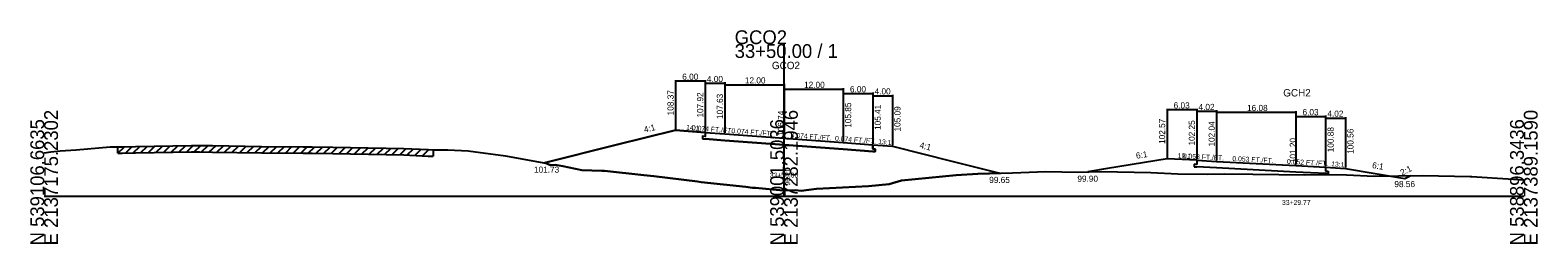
# Model space of a CAD drawing. Extents: x -14327 to 8886, y -10 to 39048.
# Drawn here: x 997.2 to 1302.8, y 6990.3 to 7033.7 of the extents above; entities that cross this region are included whole.
import ezdxf

# ---------------------------------------------------------------- set-up
doc = ezdxf.new("R2010")
doc.units = 0
for name, color, linetype in [('Level 20', 7, 'Continuous'), ('Level 5', 7, 'Continuous'), ('Level 53', 7, 'Continuous'), ('Level 54', 7, 'Continuous'), ('Level 55', 7, 'Continuous'), ('Level 7', 7, 'Continuous'), ('RD_GPK_XS_Cell', 7, 'Continuous'), ('RD_XS_EwShp', 7, 'Continuous'), ('RD_XS_ExGround', 7, 'Continuous'), ('RD_XS_ExPaveRet', 7, 'Continuous'), ('RD_XS_Pave', 7, 'Continuous'), ('RD_XS_TX_Baseline', 7, 'Continuous'), ('RD_XS_TX_Elev_EX', 7, 'Continuous'), ('RD_XS_TX_Elev_PR', 7, 'Continuous'), ('RD_XS_TX_Station', 7, 'Continuous')]:
    doc.layers.add(name, color=color, linetype=linetype)

msp = doc.modelspace()

# ---------------------------------------------------------------- linework, layer by layer
at = {"layer": 'Level 20'}
for p, q in [((1227.66, 7017.72), (1227.66, 7007.77)), ((1233.69, 7017.52), (1227.66, 7017.52)), ((1233.69, 7017.72), (1233.69, 7007.45)), ((1233.69, 7017.4), (1233.69, 7007.45)), ((1233.69, 7017.2), (1237.71, 7017.2)), ((1237.71, 7017.4), (1237.71, 7007.24)), ((1237.71, 7017.19), (1237.71, 7007.24)), ((1237.71, 7016.99), (1253.79, 7016.99)), ((1253.79, 7017.19), (1253.79, 7006.4)), ((1253.79, 7016.35), (1253.79, 7006.4)), ((1253.79, 7016.15), (1259.82, 7016.15)), ((1259.82, 7016.35), (1259.82, 7006.08)), ((1259.82, 7016.03), (1259.82, 7006.08)), ((1259.82, 7015.83), (1263.84, 7015.83)), ((1263.84, 7016.03), (1263.84, 7005.76)), ((1227.66, 7007.57), (1215.61, 7005.57)), ((1233.69, 7007.25), (1227.66, 7007.57)), ((1233.19, 7006.45), (1233.19, 7005.95)), ((1233.69, 7006.42), (1233.19, 7006.45)), ((1233.69, 7007.25), (1233.69, 7006.42)), ((1233.69, 7007.25), (1237.71, 7007.04)), ((1237.71, 7007.04), (1253.79, 7006.2)), ((1215.61, 7005.57), (1211.59, 7004.9)), ((1233.19, 7005.95), (1233.69, 7005.92)), ((1237.71, 7005.71), (1233.69, 7005.92)), ((1253.79, 7004.86), (1237.71, 7005.71)), ((1253.79, 7006.2), (1259.82, 7005.88)), ((1259.82, 7004.55), (1253.79, 7004.86)), ((1259.82, 7005.88), (1259.82, 7005.05)), ((1259.82, 7005.88), (1263.84, 7005.56)), ((1259.82, 7005.05), (1260.33, 7005.02)), ((1260.33, 7004.52), (1259.82, 7004.55)), ((1260.33, 7005.02), (1260.33, 7004.52)), ((1263.84, 7005.56), (1275.9, 7003.56)), ((1275.9, 7003.56), (1277.1, 7004.16))]:
    msp.add_line(p, q, dxfattribs=at)
at = {"layer": 'Level 5'}
for p, q in [((1134, 7012.92), (1134, 7012.09)), ((1133.5, 7012.13), (1133.5, 7011.63)), ((1134, 7012.09), (1133.5, 7012.13)), ((1133.5, 7011.63), (1134, 7011.59)), ((1138, 7011.29), (1134, 7011.59)), ((1150, 7010.4), (1138, 7011.29)), ((1162, 7009.52), (1150, 7010.4)), ((1168, 7009.07), (1162, 7009.52)), ((1168, 7010.41), (1168, 7009.57)), ((1168, 7009.57), (1168.5, 7009.54)), ((1168.5, 7009.54), (1168.5, 7009.04)), ((1168.5, 7009.04), (1168, 7009.07))]:
    msp.add_line(p, q, dxfattribs=at)
at = {"layer": 'Level 54'}
for p, q in [((1128, 7023.52), (1128, 7013.57)), ((1134, 7023.32), (1128, 7023.32)), ((1134, 7023.52), (1134, 7013.12)), ((1134, 7023.07), (1134, 7013.12)), ((1134, 7022.87), (1138, 7022.87)), ((1138, 7023.07), (1138, 7012.83)), ((1138, 7022.78), (1138, 7012.83)), ((1138, 7022.58), (1150, 7022.58)), ((1150, 7022.78), (1150, 7011.94)), ((1150, 7021.89), (1150, 7011.94)), ((1150, 7021.69), (1162, 7021.69)), ((1162, 7021.89), (1162, 7011.05)), ((1162, 7021), (1162, 7011.05)), ((1162, 7020.8), (1168, 7020.8)), ((1168, 7021), (1168, 7010.61)), ((1168, 7020.56), (1168, 7010.61)), ((1168, 7020.36), (1172, 7020.36)), ((1172, 7020.56), (1172, 7010.29))]:
    msp.add_line(p, q, dxfattribs=at)
at = {"layer": 'Level 7'}
for p, q in [((1128, 7013.37), (1116, 7010.37)), ((1134, 7012.92), (1128, 7013.37)), ((1116, 7010.37), (1101.45, 7006.73)), ((1168, 7010.41), (1172, 7010.09)), ((1172, 7010.09), (1184, 7007.09)), ((1184, 7007.09), (1193.74, 7004.65))]:
    msp.add_line(p, q, dxfattribs=at)
at = {"layer": 'RD_GPK_XS_Cell'}
for p, q in [((1150, 7000), (1150, 7030.81)), ((1000, 7000), (1150, 7000)), ((1150, 7000), (1300, 7000))]:
    msp.add_line(p, q, dxfattribs=at)
at = {"layer": 'RD_XS_EwShp'}
msp.add_lwpolyline([(1133.5, 7011.63), (1134, 7011.59), (1138, 7011.29), (1150, 7010.4), (1162, 7009.52), (1168, 7009.07), (1168.5, 7009.04), (1168.5, 7009.54), (1168, 7009.57), (1168, 7010.41), (1172, 7010.09), (1184, 7007.09), (1193.74, 7004.65), (1189.32, 7004.52), (1184.93, 7004.24), (1173.79, 7003.13), (1171.3, 7002.44), (1167.12, 7002.04), (1156.56, 7001.5), (1153.49, 7001.09), (1152.34, 7001.17), (1149.83, 7001.1), (1144.23, 7001.67), (1143.64, 7001.7), (1142.28, 7001.86), (1133.22, 7002.81), (1132.47, 7002.92), (1123.6, 7004.05), (1121.61, 7004.25), (1113.6, 7005.09), (1113.04, 7005.09), (1109.04, 7005.22), (1105.15, 7006.05), (1103.67, 7006.35), (1102.69, 7006.29), (1101.68, 7006.69), (1101.45, 7006.73), (1116, 7010.37), (1128, 7013.37), (1134, 7012.92), (1134, 7012.09), (1133.5, 7012.13)], close=True, dxfattribs=at)
at = {"layer": 'RD_XS_ExGround'}
for p, q in [((1003.23, 7009.16), (1006.47, 7009.37)), ((1006.47, 7009.37), (1013.36, 7010)), ((1013.36, 7010), (1014.93, 7009.97)), ((1014.93, 7009.97), (1015.82, 7009.99)), ((1015.82, 7009.99), (1018.52, 7010.06)), ((1018.52, 7010.06), (1029.84, 7010.24)), ((1029.84, 7010.24), (1031.46, 7010.27)), ((1031.46, 7010.27), (1034.1, 7010.23)), ((1034.1, 7010.23), (1044.07, 7010.08)), ((1044.07, 7010.08), (1052.51, 7010)), ((1052.51, 7010), (1054.35, 7009.97)), ((1054.35, 7009.97), (1058.55, 7009.9)), ((1058.55, 7009.9), (1072.92, 7009.67)), ((1072.92, 7009.67), (1077.83, 7009.42)), ((1077.83, 7009.42), (1078.88, 7009.37)), ((1078.88, 7009.37), (1081.85, 7009.35)), ((1081.85, 7009.35), (1085.98, 7009.15)), ((1000, 7008.78), (1001.38, 7008.95)), ((1001.38, 7008.95), (1003.23, 7009.16)), ((1085.98, 7009.15), (1093.5, 7008.17)), ((1093.5, 7008.17), (1093.84, 7008.11)), ((1093.84, 7008.11), (1101.68, 7006.69)), ((1101.68, 7006.69), (1102.69, 7006.29)), ((1102.69, 7006.29), (1103.67, 7006.35)), ((1103.67, 7006.35), (1105.15, 7006.05)), ((1105.15, 7006.05), (1109.04, 7005.22)), ((1109.04, 7005.22), (1113.04, 7005.09)), ((1113.04, 7005.09), (1113.6, 7005.09)), ((1113.6, 7005.09), (1121.61, 7004.25)), ((1121.61, 7004.25), (1123.6, 7004.05)), ((1123.6, 7004.05), (1132.47, 7002.92)), ((1173.79, 7003.13), (1184.93, 7004.24)), ((1184.93, 7004.24), (1189.32, 7004.52)), ((1189.32, 7004.52), (1196.33, 7004.73)), ((1196.33, 7004.73), (1203.07, 7004.95)), ((1203.07, 7004.95), (1209.6, 7004.86)), ((1209.6, 7004.86), (1214.22, 7004.96)), ((1214.22, 7004.96), (1224.39, 7004.75)), ((1224.39, 7004.75), (1229.82, 7004.49)), ((1229.82, 7004.49), (1235.87, 7004.46)), ((1235.87, 7004.46), (1239.24, 7004.48)), ((1239.24, 7004.48), (1245.06, 7004.47)), ((1245.06, 7004.47), (1255.59, 7004.31)), ((1255.59, 7004.31), (1259.61, 7004.4)), ((1259.61, 7004.4), (1264.04, 7004.31)), ((1264.04, 7004.31), (1269.64, 7004.03)), ((1269.64, 7004.03), (1279.54, 7004.2)), ((1279.54, 7004.2), (1289.09, 7003.97)), ((1289.09, 7003.97), (1289.47, 7003.97)), ((1289.47, 7003.97), (1291.46, 7003.83)), ((1291.46, 7003.83), (1300, 7003.29)), ((1132.47, 7002.92), (1133.22, 7002.81)), ((1133.22, 7002.81), (1142.28, 7001.86)), ((1142.28, 7001.86), (1143.64, 7001.7)), ((1143.64, 7001.7), (1144.23, 7001.67)), ((1144.23, 7001.67), (1149.83, 7001.1)), ((1149.83, 7001.1), (1152.34, 7001.17)), ((1152.34, 7001.17), (1153.49, 7001.09)), ((1153.49, 7001.09), (1156.56, 7001.5)), ((1156.56, 7001.5), (1167.12, 7002.04)), ((1167.12, 7002.04), (1171.3, 7002.44)), ((1171.3, 7002.44), (1173.79, 7003.13))]:
    msp.add_line(p, q, dxfattribs=at)
at = {"layer": 'RD_XS_ExPaveRet'}
for p, q in [((1014.93, 7008.67), (1016.3, 7010)), ((1014.93, 7008.67), (1014.93, 7009.97)), ((1016.47, 7008.71), (1017.85, 7010.04)), ((1018.02, 7008.75), (1019.39, 7010.08)), ((1019.56, 7008.78), (1020.92, 7010.1)), ((1021.11, 7008.8), (1022.47, 7010.12)), ((1022.65, 7008.83), (1024.01, 7010.15)), ((1024.2, 7008.85), (1025.56, 7010.17)), ((1025.74, 7008.88), (1027.1, 7010.2)), ((1027.29, 7008.9), (1028.65, 7010.22)), ((1028.83, 7008.92), (1030.19, 7010.25)), ((1030.38, 7008.95), (1031.73, 7010.27)), ((1031.92, 7008.96), (1033.24, 7010.24)), ((1033.47, 7008.94), (1034.79, 7010.22)), ((1035.01, 7008.91), (1036.33, 7010.2)), ((1036.56, 7008.89), (1037.88, 7010.17)), ((1038.1, 7008.87), (1039.42, 7010.15)), ((1039.65, 7008.85), (1040.97, 7010.13)), ((1041.19, 7008.83), (1042.51, 7010.11)), ((1042.74, 7008.8), (1044.06, 7010.08)), ((1044.28, 7008.78), (1045.61, 7010.07)), ((1045.83, 7008.77), (1047.15, 7010.05)), ((1047.37, 7008.75), (1048.7, 7010.04)), ((1048.92, 7008.73), (1050.24, 7010.02)), ((1050.46, 7008.72), (1051.78, 7010)), ((1052.01, 7008.7), (1053.33, 7009.98)), ((1053.55, 7008.68), (1054.87, 7009.96)), ((1055.09, 7008.66), (1056.41, 7009.94)), ((1056.64, 7008.63), (1057.96, 7009.91)), ((1058.18, 7008.61), (1059.5, 7009.89)), ((1059.73, 7008.58), (1061.05, 7009.86)), ((1061.27, 7008.56), (1062.59, 7009.84)), ((1062.82, 7008.53), (1064.14, 7009.81)), ((1064.36, 7008.51), (1065.68, 7009.79)), ((1065.91, 7008.48), (1067.23, 7009.76)), ((1067.45, 7008.46), (1068.77, 7009.74)), ((1069, 7008.44), (1070.32, 7009.72)), ((1070.54, 7008.41), (1071.86, 7009.69)), ((1072.09, 7008.39), (1073.39, 7009.65)), ((1073.63, 7008.34), (1074.9, 7009.57)), ((1075.18, 7008.26), (1076.45, 7009.49)), ((1076.72, 7008.18), (1077.99, 7009.42)), ((1078.88, 7009.37), (1078.88, 7008.07)), ((1014.93, 7008.67), (1015.82, 7008.69)), ((1015.82, 7008.69), (1018.52, 7008.76)), ((1018.52, 7008.76), (1029.84, 7008.94)), ((1029.84, 7008.94), (1031.46, 7008.97)), ((1031.46, 7008.97), (1034.1, 7008.93)), ((1034.1, 7008.93), (1044.07, 7008.78)), ((1044.07, 7008.78), (1052.51, 7008.7)), ((1052.51, 7008.7), (1054.35, 7008.67)), ((1054.35, 7008.67), (1058.55, 7008.6)), ((1058.55, 7008.6), (1072.92, 7008.37)), ((1072.92, 7008.37), (1077.83, 7008.12)), ((1077.83, 7008.12), (1078.88, 7008.07))]:
    msp.add_line(p, q, dxfattribs=at)
at = {"layer": 'RD_XS_Pave'}
for p, q in [((1134, 7012.92), (1138, 7012.63)), ((1138, 7012.63), (1150, 7011.74)), ((1150, 7011.74), (1162, 7010.85)), ((1162, 7010.85), (1168, 7010.41))]:
    msp.add_line(p, q, dxfattribs=at)

# ---------------------------------------------------------------- texts
at = {"layer": 'Level 20'}
for s, height, p in [('GCH2', 1.5, (1251.22, 7020.2)), ('6.03', 1.25, (1229, 7017.77)), ('4.02', 1.25, (1234.04, 7017.45)), ('16.08', 1.25, (1243.88, 7017.24)), ('6.03', 1.25, (1255.13, 7016.4)), ('4.02', 1.25, (1260.17, 7016.08)), ('99.90', 1.25, (1209.48, 7002.9)), ('98.56', 1.25, (1273.75, 7001.81)), ('33+29.77', 1, (1250.97, 6998.2))]:
    msp.add_text(s, height=height, dxfattribs=at).set_placement(p)
for s, height, rotation, p in [('102.57', 1.25, 90, (1227.28, 7010.57)), ('102.25', 1.25, 90, (1233.31, 7010.25)), ('102.04', 1.25, 90, (1237.33, 7010.04)), ('100.88', 1.25, 90, (1261.45, 7008.88)), ('100.56', 1.25, 90, (1265.47, 7008.56)), (' 101.20', 1.25, 90, (1253.79, 7006.2)), ('6:1', 1.25, 9.4169, (1221.47, 7007.55)), ('19:1', 1, 357.0076, (1229.79, 7007.71)), ('0.053 FT./FT.', 1, 356.9929, (1230.84, 7007.65)), ('0.053 FT./FT.', 1, 356.994, (1240.89, 7007.13)), ('0.052 FT./FT.', 1, 356.9953, (1251.96, 7006.54)), ('13:1', 1, 355.4491, (1260.9, 7006.05)), ('6:1', 1.25, 350.5847, (1269.17, 7005.69)), ('2:1', 1.25, 26.449, (1275.33, 7004.11))]:
    msp.add_text(s, height=height, rotation=rotation, dxfattribs=at).set_placement(p)
at = {"layer": 'Level 53'}
for s, rotation, p in [('108.37', 90, (1127.62, 7016.37)), ('107.92', 90, (1133.62, 7015.92)), ('107.63', 90, (1137.62, 7015.63)), ('105.85', 90, (1163.62, 7013.85)), ('105.41', 90, (1169.62, 7013.41)), ('105.09', 90, (1173.62, 7013.09)), ('4:1', 14.0362, (1121.76, 7012.84)), ('4:1', 345.9638, (1177.39, 7009.77))]:
    msp.add_text(s, height=1.25, rotation=rotation, dxfattribs=at).set_placement(p)
for s, p in [('101.73', (1099.31, 7004.73)), ('99.65', (1191.61, 7002.65))]:
    msp.add_text(s, height=1.25, dxfattribs=at).set_placement(p)
at = {"layer": 'Level 54'}
for s, p in [('6.00', (1129.37, 7023.57)), ('4.00', (1134.37, 7023.12)), ('12.00', (1142.07, 7022.83)), ('12.00', (1154.07, 7021.94)), ('6.00', (1163.37, 7021.05)), ('4.00', (1168.37, 7020.61))]:
    msp.add_text(s, height=1.25, dxfattribs=at).set_placement(p)
at = {"layer": 'Level 55'}
for s, rotation, p in [('14:1', 355.7678, (1130.12, 7013.46)), ('0.074 FT./FT.', 355.7678, (1131.31, 7013.37)), ('0.074 FT./FT.', 355.7678, (1139.31, 7012.78)), ('0.074 FT./FT.', 355.7678, (1151.31, 7011.89)), ('0.074 FT./FT.', 355.7678, (1160.31, 7011.23)), ('13:1', 355.4261, (1169.07, 7010.57))]:
    msp.add_text(s, height=1, rotation=rotation, dxfattribs=at).set_placement(p)
at = {"layer": 'RD_GPK_XS_Cell'}
for s, p in [('33+50.00 / 1', (1140, 7028.01)), ('GCO2', (1140, 7030.81))]:
    msp.add_text(s, height=2.8, dxfattribs=at).set_placement(p)
for s, p in [('N 539106.6635', (1000, 6990)), ('E 2137175.2302', (1002.8, 6990)), ('N 539001.5036', (1150, 6990)), ('E 2137282.1946', (1152.8, 6990)), ('N 538896.3436', (1300, 6990)), ('E 2137389.1590', (1302.8, 6990))]:
    msp.add_text(s, height=2.8, rotation=90, dxfattribs=at).set_placement(p)
at = {"layer": 'RD_XS_TX_Baseline'}
msp.add_text('GCO2', height=1.5, dxfattribs=at).set_placement((1147.55, 7025.74))
at = {"layer": 'RD_XS_TX_Elev_EX'}
msp.add_text('96.11', height=1, rotation=90, dxfattribs=at).set_placement((1151.25, 7002.11))
at = {"layer": 'RD_XS_TX_Elev_PR'}
msp.add_text(' 106.74', height=1.25, rotation=90, dxfattribs=at).set_placement((1150, 7011.74))
at = {"layer": 'RD_XS_TX_Station'}
msp.add_text('33+50.00', height=1, dxfattribs=at).set_placement((1147.1, 7003.74))

doc.saveas('drawing.dxf')
